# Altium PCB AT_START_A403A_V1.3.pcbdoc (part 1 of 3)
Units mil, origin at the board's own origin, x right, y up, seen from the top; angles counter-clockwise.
Board outline 6370 x 3956 mil, 2 copper layers (Top Layer, Bottom Layer); 182 components, 198 nets, 768 pads, 894 vias.
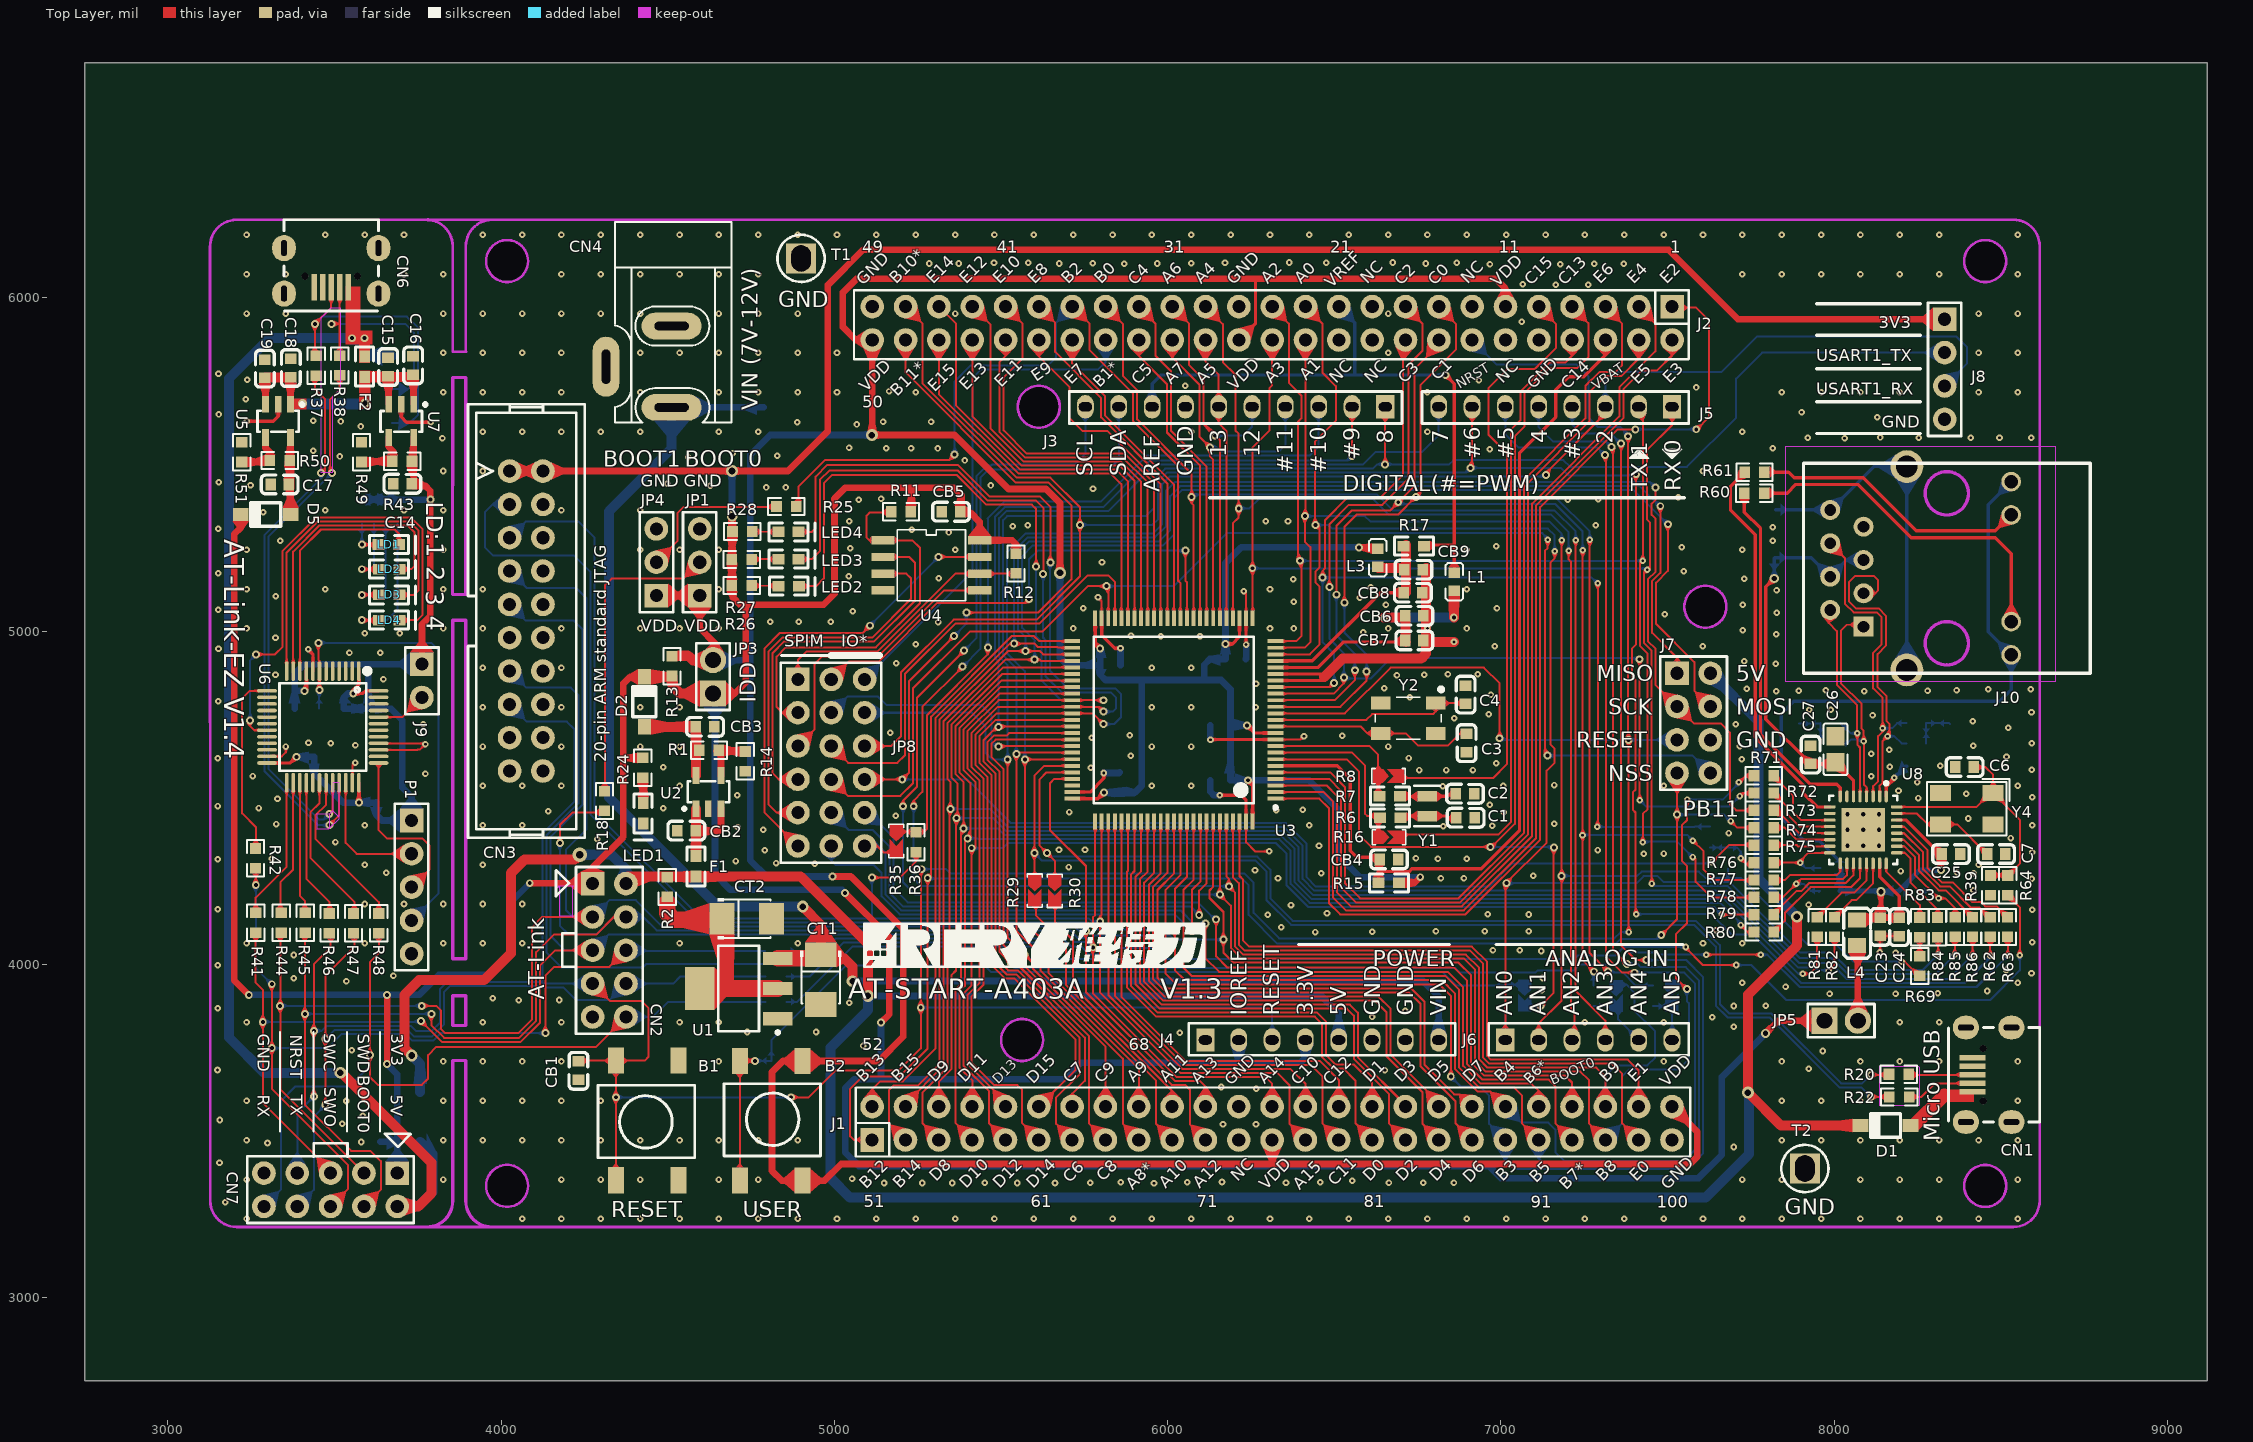
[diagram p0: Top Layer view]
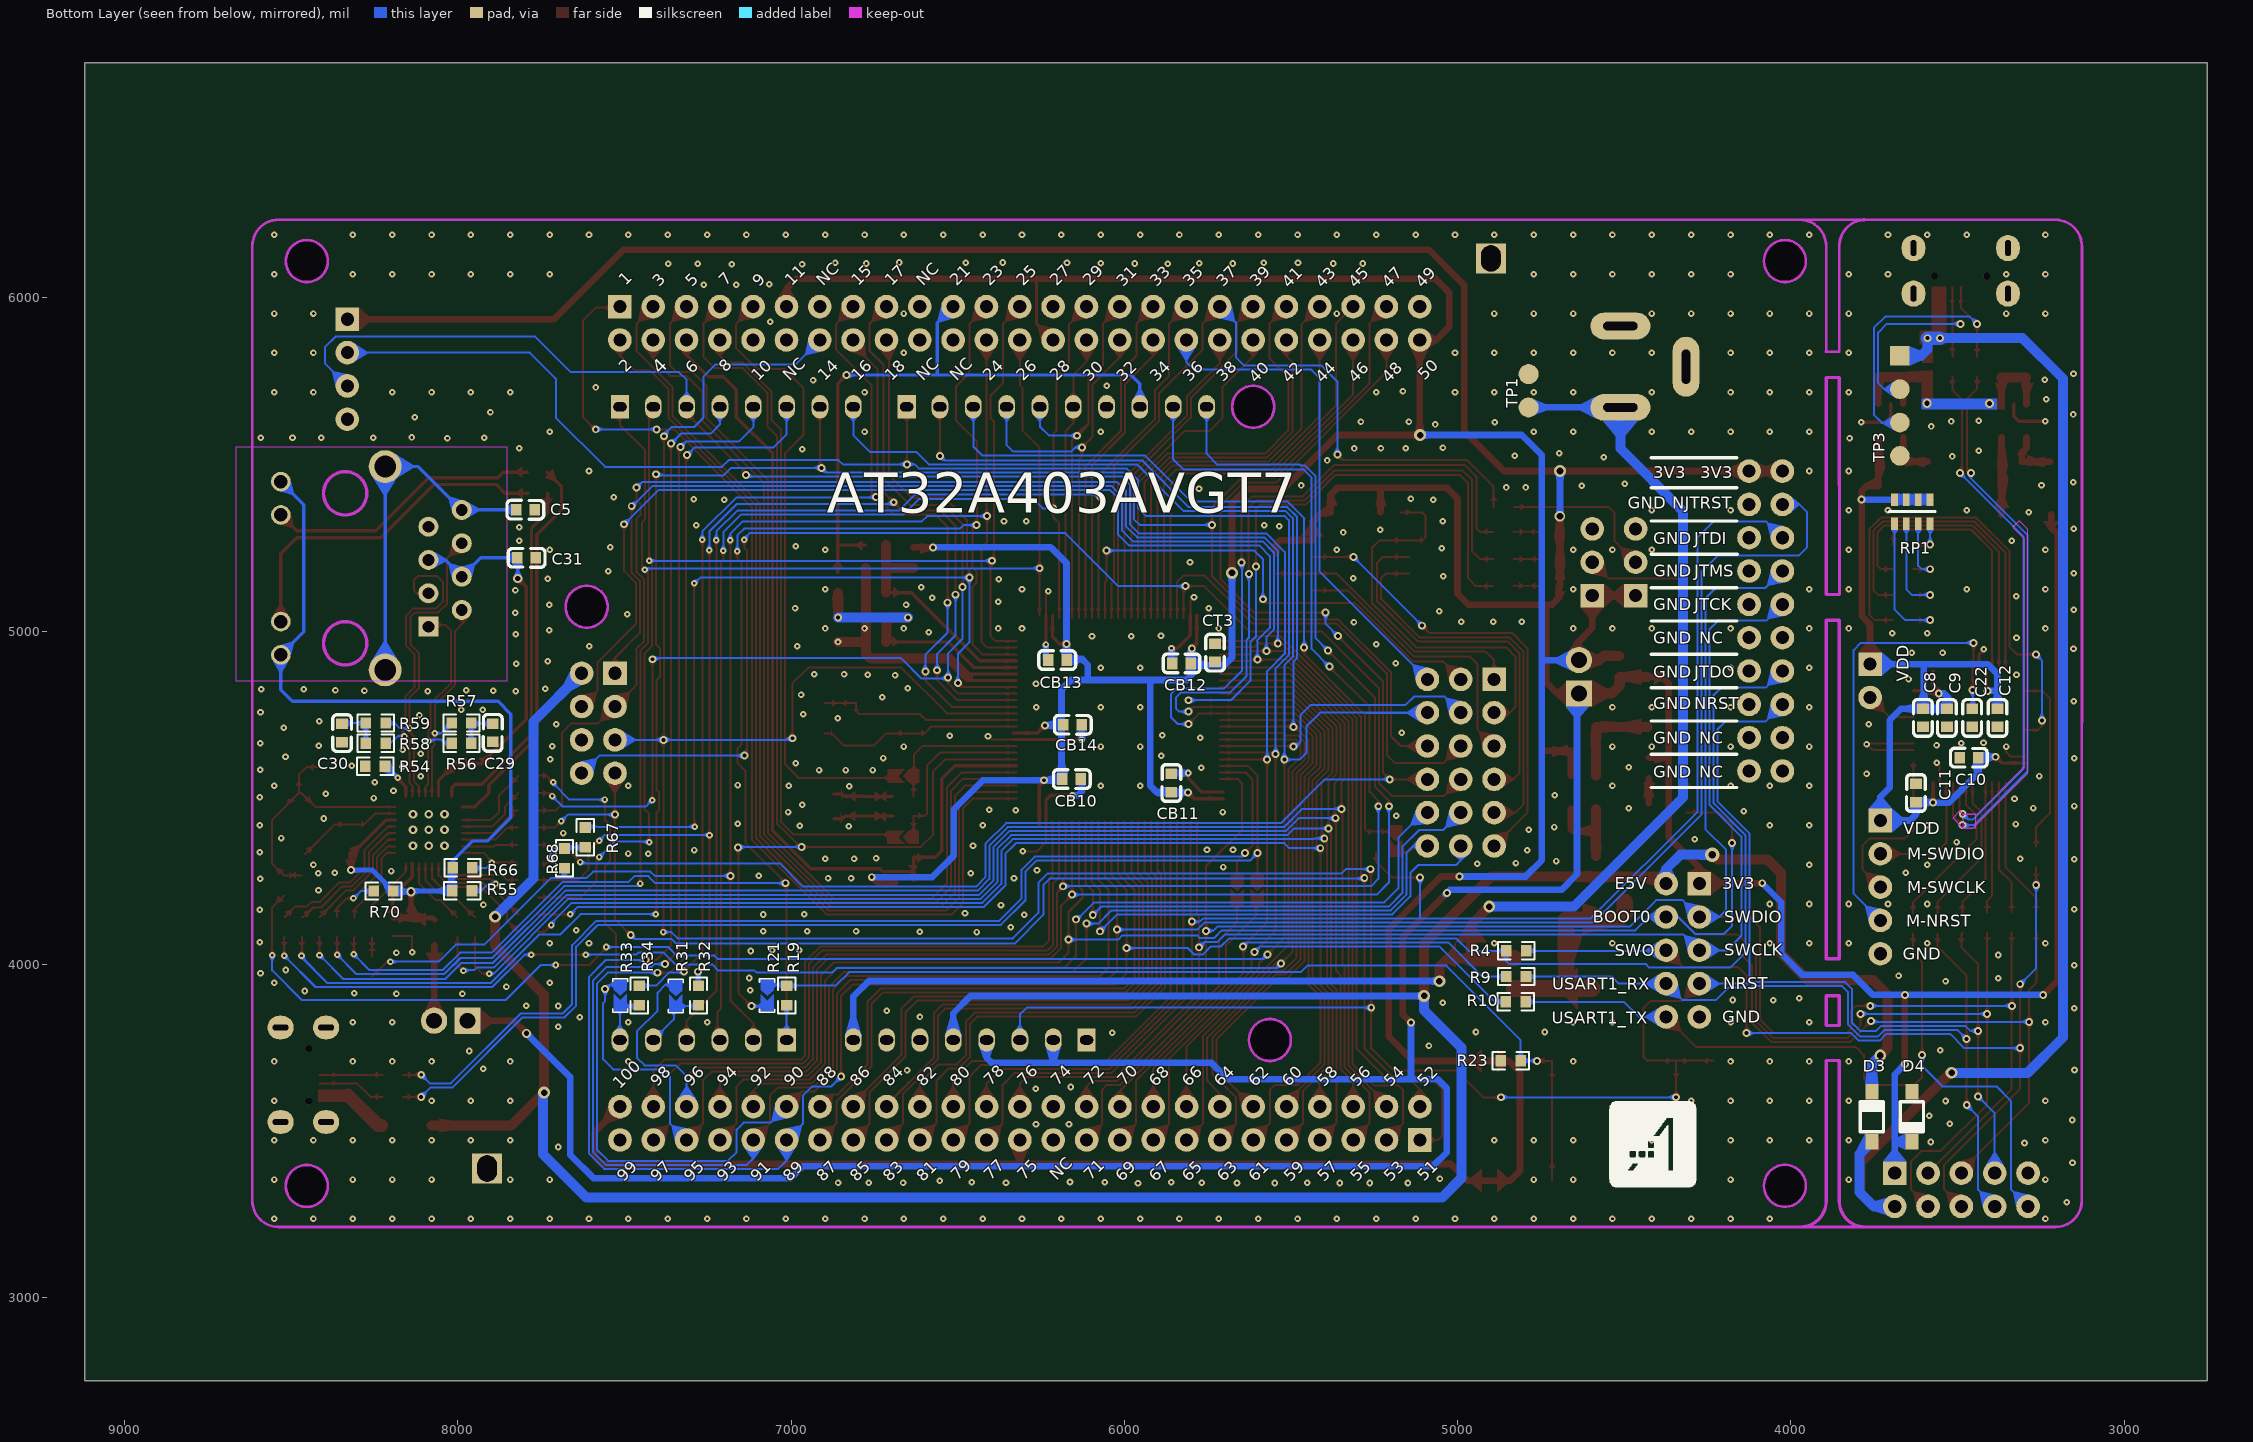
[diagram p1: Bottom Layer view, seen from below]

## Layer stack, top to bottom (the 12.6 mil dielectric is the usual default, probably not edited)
Top Layer: signal copper (thickness not stored)
Dielectric: dielectric 12.6, FR-4, Dk 4.8
Bottom Layer: signal copper (thickness not stored)

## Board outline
9120,2750 2750,2750 2750,6706 9120,6706
cut-out: 5676.27,5675.04 5676.27,5671.03 cw(c5613.28,5671.03) 5613.28,5608.03 cw(c5613.28,5673.03) 5548.28,5673.03 5548.28,5678.03 cw(c5608.28,5678.03) 5608.28,5738.03 5613.28,5738.03 cw(c5613.28,5675.04)
cut-out: 4080.65,6112.34 4080.65,6108.33 cw(c4017.66,6108.33) 4017.66,6045.33 cw(c4017.66,6110.33) 3952.66,6110.33 3952.66,6115.33 cw(c4012.66,6115.33) 4012.66,6175.33 4017.66,6175.33 cw(c4017.66,6112.34)
cut-out: 8517.27,6111.66 8517.27,6107.65 cw(c8454.28,6107.65) 8454.28,6044.65 cw(c8454.28,6109.65) 8389.28,6109.65 8389.28,6114.65 cw(c8449.28,6114.65) 8449.28,6174.65 8454.28,6174.65 cw(c8454.28,6111.66)
cut-out: 8516.42,3337.04 8516.42,3333.03 cw(c8453.43,3333.03) 8453.43,3270.03 cw(c8453.43,3335.03) 8388.43,3335.03 8388.43,3340.03 cw(c8448.43,3340.03) 8448.43,3400.03 8453.43,3400.03 cw(c8453.43,3337.04)
cut-out: 4080.65,3337.34 4080.65,3333.33 cw(c4017.66,3333.33) 4017.66,3270.33 cw(c4017.66,3335.33) 3952.66,3335.33 3952.66,3340.33 cw(c4012.66,3340.33) 4012.66,3400.33 4017.66,3400.33 cw(c4017.66,3337.34)
cut-out: 7676.27,5075.04 7676.27,5071.03 cw(c7613.28,5071.03) 7613.28,5008.03 cw(c7613.28,5073.03) 7548.28,5073.03 7548.28,5078.03 cw(c7608.28,5078.03) 7608.28,5138.03 7613.28,5138.03 cw(c7613.28,5075.04)
cut-out: 5626.27,3775.04 5626.27,3771.03 cw(c5563.28,3771.03) 5563.28,3708.03 cw(c5563.28,3773.03) 5498.28,3773.03 5498.28,3778.03 cw(c5558.28,3778.03) 5558.28,3838.03 5563.28,3838.03 cw(c5563.28,3775.04)

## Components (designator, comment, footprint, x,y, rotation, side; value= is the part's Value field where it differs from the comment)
B1 "PB,BLACK,SMD_2P" KEY_SOP_6*6 4344.58,3352.18 r90 top
B2 "PB,Blue,SMD_2P" KEY_SOP_6*6 4904.58,3710.18 r270 top
C1 "CL10C150JB8NNNC" C0603 6894,4440 r180 top
C2 "CL10C150JB8NNNC" C0603 6892,4512 r180 top
C3 "0603CG300J500NT" C0603 6897,4664 r90 top
C4 "0603CG300J500NT" C0603 6894,4809 r270 top
C5 "CC0603KRX7R9BB104" C0603 7797,5364 r180 bottom
C6 "0603CG300J500NT" C0603 8391,4592 r180 top
C7 "0603CG300J500NT" C0603 8486,4331 r0 top
C8 "CL10A475KO8NNNC" C0603 3604,4740 r90 bottom
C9 "CC0603KRX7R9BB104" C0603 3532,4740 r90 bottom
C10 "CC0603KRX7R9BB104" C0603 3466,4620 r180 bottom
C11 "CC0603KRX7R9BB104" C0603 3625,4514 r270 bottom
C12 "CC0603KRX7R9BB104" C0603 3380,4740 r90 bottom
C14 "CL10A106MA8NRNC" C0603 3704,5442 r0 top
C15 "CL10A106MA8NRNC" C0603 3661,5792 r270 top
C16 "CC0603KRX7R9BB104" C0603 3736,5797 r270 top
C17 "CL10A106MA8NRNC" C0603 3336,5440 r0 top
C18 "CL10A106MA8NRNC" C0603 3369,5789 r270 top
C19 "CC0603KRX7R9BB104" C0603 3291,5787 r270 top
C22 "CC0603KRX7R9BB104" C0603 3456,4740 r90 bottom
C23 "CL10A475KO8NNNC" C0603 8138,4113 r90 top
C24 "CC0603KRX7R9BB104" C0603 8195,4112 r90 top
C25 "CC0603KRX7R9BB104" C0603 8350,4331 r180 top
C26 "CL21A476MQYNNNE" C0805 8004,4645.37 r270 top
C27 "CC0603KRX7R9BB104" C0603 7929,4629 r270 top
C29 "CC0603KRX7R9BB104" C0603 7895,4695 r90 bottom
C30 "CC0603KRX7R9BB104" C0603 8347,4694 r90 bottom
C31 "CC0603KRX7R9BB104" C0603 7793.44,5220 r0 bottom
CB1 "CC0603KRX7R9BB104" C0603 4232,3681 r90 top
CB2 "CL10A105KB8NNNC" C0603 4556,4401 r0 top
CB3 "CL10A105KB8NNNC" C0603 4612,4713 r180 top
CB4 "CL10A105KB8NNNC" C0603 6664,4315 r180 top
CB5 "CC0603KRX7R9BB104" C0603 5350,5358 r0 top
CB6 "CL10A105KB8NNNC" C0603 6740,5046 r180 top
CB7 "CC0603KRX7R9BB104" C0603 6740,4972 r180 top
CB8 "CL10A105KB8NNNC" C0603 6736,5115 r0 top
CB9 "CC0603KRX7R9BB104" C0603 6738,5184 r0 top
CB10 "CC0603KRX7R9BB104" C0603 6158,4556 r0 bottom
CB11 "CC0603KRX7R9BB104" C0603 5859,4544 r270 bottom
CB12 "CC0603KRX7R9BB104" C0603 5828,4903 r180 bottom
CB13 "CC0603KRX7R9BB104" C0603 6201,4913 r180 bottom
CB14 "CC0603KRX7R9BB104" C0603 6155,4719 r0 bottom
CN1 "USB micro-B" USB_MIC_DIP 8414.55,3668.76 r0 top
CN2 "CON10A" HDR2X5 4274.58,4242.18 r270 top
CN3 "10X2P" JTAG_20 4075.58,5030.18 r270 top
CN4 "DC_JACK" DC10B 4341.58,6090.28 r270 top
CN6 "USB_micro B" USB_MIC_DIP 3490.36,6032.02 r90 top
CN7 "CON1" HDR2X5 3688.43,3373.78 r180 top
CT1 "CA45-B025K106T" CAP-SMD_L3.5-W2.8-R-RD 4959,3954 r90 top
CT2 "CA45-B025K106T" CAP-SMD_L3.5-W2.8-R-RD 4737,4137 r180 top
CT3 "CL10A475KO8NNNC" C0603 5728,4935 r270 bottom
D1 "DFLS130L" SOD-123 8153.95,3516.5 r0 top
D2 "DFLS130L" SOD-123 4429.95,4787.59 r270 top
D3 "DFLS130L" SOD-123 3756.95,3542.5 r270 bottom
D4 "SMF3.3A" SOD-123 3636.95,3542.5 r90 bottom
D5 "DFLS130L" SOD-123 3294.01,5349.78 r0 top
F1 "SMD0603B025TF" R0603#1 4585.16,4263.54 r90 top
F2 "SMD0603B025TF" R0603#1 3590.43,5823.67 r270 top
J1 "CONN EDGE 25X2" HEAD2*25 5113.28,3473.03 r0 top
J2 "CONN EDGE 25X2" HEAD2*25 7513.71,5973.46 r180 top
J3 "CON10" "HDR1X10 - 2#" 6653.28,5673.03 r180 top
J4 "CON8" "HDR1X8 - 2#" 6113.28,3773.03 r0 top
J5 "CON8" "HDR1X8 - 2#" 7513.28,5673.03 r180 top
J6 "CON6" "HDR1X6 -2#" 7013.28,3773.03 r0 top
J7 "CON8A" HDR2X4 7528.28,4873.61 r270 top
J8 "Header 4" HDR1X4 8331.46,5935.5 r270 top
J9 "1X2P_2.54M" HDR1X2 3762.43,4900.78 r270 top
J10 "RJ45 (TRJ201)" HR911105A 8338.04,5188.5 r270 top
JP1 "1X3P_2.54M" HDR1X3 4595.95,5106.5 r90 top
JP3 "1X2P_2.54M" HDR-TH_2P-P2.54-V-M 4636,4863 r90 top
JP4 "1X3P_2.54M" HDR1X3 4465.95,5106.5 r90 top
JP5 "1X2P_2.54M" HDR-TH_2P-P2.54-V-M 8021,3831 r0 top
JP8 "CON3*6" HDR3X6 4890.58,4855.18 r270 top
L1 "GZ1608D601TF" L0603 6860,5148 r270 top
L3 "GZ1608D601TF" L0603 6630,5220 r270 top
L4 "GZ2012D601TF" L0805 8069,4095 r90 top
LD1 "RED" LED0603 3632.47,5259.58 r0 top
LD2 "GREEN" LED0603 3633.43,5185.48 r0 top
LD3 "BLUE" LED0603 3633.47,5108.58 r0 top
LD4 "YELLOW" LED0603 3633.43,5032.58 r0 top
LED1 "RED" LED0603 4426.13,4483.46 r270 top
LED2 "RED" LED0603 4832.62,5134.61 r0 top
LED3 "YELLOW" LED0603 4831.95,5215.39 r0 top
LED4 "GREEN" LED0603 4831.62,5297.61 r0 top
P1 "Header 5" HDR1X5 3731.43,4431.78 r270 top
R1 "0603WAF5102T5E" R0603#2 4624,4642 r0 top
R2 "0603WAF0000T5E" R0603#2 4498.9,4232.03 r90 top
R4 "0603WAF4700T5E" R0603#2 4823.95,4040.5 r180 bottom
R6 "0603WAF0000T5E" R0603#1 6698,4440 r180 top
R7 "0603WAF0000T5E" R0603#1 6697,4505 r180 top
R8 "NC_SB-PAD" SB-PAD 6663,4565 r0 top
R9 "0603WAF4700T5E" R0603#2 4824.42,3963.51 r180 bottom
R10 "0603WAF4700T5E" R0603#2 4825.42,3887.51 r180 bottom
R11 "0603WAF1002T5E" R0603#2 5200,5358 r180 top
R12 "0603WAF1002T5E" R0603#2 5545,5203 r270 top
R13 "0603WAF0000T5E" R0603#2 4513,4895 r90 top
R14 "0603WAF1502T5E" R0603#2 4733,4609 r270 top
R15 "0603WAF0000T5E" R0603#1 6694,4245 r180 top
R16 "NC_SB-PAD" SB-PAD 6664,4381 r0 top
R17 "0603WAF0000T5E" R0603#1 6769,5255 r180 top
R18 "0603WAF1002T5E" R0603#2 4310,4490 r90 top
R19 "0603WAF0000T5E" R0603#2 7013.33,3906.35 r90 bottom
R20 "0603WAF220JT5E" R0603#2 8194,3670 r0 top
R21 "NC_SB-PAD" SB-PAD 7072,3906.28 r270 bottom
R22 "0603WAF220JT5E" R0603#2 8195,3602 r0 top
R23 "0603WAF1003T5E" R0603#2 4840.66,3711 r0 bottom
R24 "0603WAF1001T5E" R0603#2 4425,4590 r90 top
R25 "0603WAF1002T5E" R0603#2 4856,5374 r0 top
R26 "0603WAF1001T5E" R0603#2 4722,5137 r180 top
R27 "0603WAF1001T5E" R0603#2 4722,5215 r180 top
R28 "0603WAF1001T5E" R0603#2 4724,5299 r180 top
R29 "NC_SB-PAD" SB-PAD 5601,4221 r270 top
R30 "NC_SB-PAD" SB-PAD 5661,4220.72 r270 top
R31 "NC_SB-PAD" SB-PAD 7346,3905 r270 bottom
R32 "0603WAF0000T5E" R0603#2 7277.78,3906.66 r90 bottom
R33 "NC_SB-PAD" SB-PAD 7513,3907 r270 bottom
R34 "0603WAF0000T5E" R0603#2 7455.95,3906.65 r90 bottom
R35 "NC_SB-PAD" SB-PAD 5186,4370 r270 top
R36 "0603WAF0000T5E" R0603#2 5244.95,4366.5 r90 top
R37 "0603WAF220JT5E" R0603#2 3445,5796 r90 top
R38 "0603WAF220JT5E" R0603#2 3516,5797 r90 top
R39 "0603WAF1003T5E" R0603#2 8469,4237 r270 top
R41 "0603WAF330JT5E" R0603#2 3264,4125 r270 top
R42 "0603WAF330JT5E" R0603#2 3263,4318 r270 top
R43 "0603WAF4702T5E" R0603#2 3703,5510 r180 top
R44 "0603WAF330JT5E" R0603#2 3340,4125 r270 top
R45 "0603WAF330JT5E" R0603#2 3412,4125 r270 top
R46 "0603WAF330JT5E" R0603#2 3484,4123 r270 top
R47 "0603WAF330JT5E" R0603#2 3557,4123 r270 top
R48 "0603WAF330JT5E" R0603#2 3633,4123 r270 top
R49 "0603WAF1502T5E" R0603#2 3581,5537 r90 top
R50 "0603WAF5102T5E" R0603#2 3336,5512 r180 top
R51 "0603WAF1502T5E" R0603#2 3222,5537 r90 top
R54 "0603WAF6801T5E" R0603#2 8248,4594 r180 bottom
R55 "0603WAF1501T5E" R0603#2 7987,4221 r180 bottom
R56 "0603WAF499JT5E" R0603#2 7989,4663 r0 bottom
R57 "0603WAF499JT5E" R0603#2 7989,4724 r0 bottom
R58 "0603WAF499JT5E" R0603#2 8246,4663 r180 bottom
R59 "0603WAF499JT5E" R0603#2 8246,4724 r180 bottom
R60 "0603WAF3300T5E" R0603#2 7760,5414 r0 top
R61 "0603WAF3300T5E" R0603#2 7761,5477 r0 top
R62 "0603WAF0000T5E" R0603#2 8468,4112 r90 top
R63 "0603WAF499JT5E" R0603#2 8520,4112 r270 top
R64 "0603WAF499JT5E" R0603#2 8521,4237 r270 top
R66 "0603WAF4701T5E" R0603#2 7986,4290 r180 bottom
R67 "0603WAF0000T5E" R0603#2 7618,4381 r90 bottom
R68 "0603WAF0000T5E" R0603#2 7680,4318 r90 bottom
R69 "0603WAF0000T5E" R0603#2 8257,3995 r270 top
R70 "0603WAF4701T5E" R0603#2 8223,4220 r0 bottom
R71 "0603WAF0000T5E" R0603#2 7789,4566 r180 top
R72 "0603WAF0000T5E" R0603#2 7789,4514 r180 top
R73 "0603WAF0000T5E" R0603#2 7789,4462 r180 top
R74 "0603WAF0000T5E" R0603#2 7789,4410 r180 top
R75 "0603WAF0000T5E" R0603#2 7788.98,4357.53 r180 top
R76 "0603WAF0000T5E" R0603#2 7789,4305 r180 top
R77 "0603WAF0000T5E" R0603#2 7789,4253 r180 top
R78 "0603WAF0000T5E" R0603#2 7789,4201 r180 top
R79 "0603WAF0000T5E" R0603#2 7789,4149 r180 top
R80 "0603WAF0000T5E" R0603#2 7789,4097 r180 top
R81 "0603WAF0000T5E" R0603#2 7949,4112 r90 top
R82 "0603WAF0000T5E" R0603#2 8001,4112 r90 top
R83 "0603WAF0000T5E" R0603#2 8257,4111 r90 top
R84 "0603WAF0000T5E" R0603#2 8310,4111 r90 top
R85 "0603WAF0000T5E" R0603#2 8363,4112 r90 top
R86 "0603WAF0000T5E" R0603#2 8415,4112 r90 top
RP1 "1K" RP_4-0603 3688.82,5321.66 r90 bottom
T1 "Socket" TestPoint 4899.95,6118.29 r270 top
T2 "Socket" TestPoint 7911.95,3387.5 r270 top
TP1 "1X2P_2.54M" TEST_PAD_1x2p_2.54 4787,5721 r90 bottom
TP3 "1X4P_2.54F" "HDR1X4 - TOP" 3673.01,5825.78 r270 bottom
U1 "AMS1117-5.0" SOT223 4712.95,3927.5 r180 top
U2 "RT9080N-08GJ5" SOT-23-5 4684.95,4531.5 r90 top
U3 "AT32F407VGT7" LQFP100_14*14 6018.62,4733.5 r180 top
U4 "EN25QH128A" SOIC8_208 5290.95,5197.5 r270 top
U5 "RT9080N-08GJ5" SOT-23-5 3268.23,5615.67 r270 top
U6 "AT32F403ACCT7" LQFP-48_L7.0-W7.0-P0.50-LS9.0-BL 3464.9,4712.46 r180 top
U7 "RT9080N-08GJ5" SOT-23-5 3637.43,5615.6 r270 top
U8 "DM9162NP" DM9162NP 8087.21,4403.5 r270 top
Y1 "32.768KHz" "XTAL_SOP - FC-12M" 6778.58,4504.18 r270 top
Y2 "8MHz" SMD_5032_4P 6721.95,4738.5 r180 top
Y4 "X503225MSB4SI" CRYSTAL-SMD_4P-L5.0-W3.2-BL 8398,4467 r180 top

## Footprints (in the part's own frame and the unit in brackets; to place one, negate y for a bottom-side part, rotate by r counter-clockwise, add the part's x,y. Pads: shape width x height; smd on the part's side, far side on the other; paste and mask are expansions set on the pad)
C0603 [mm]
  rect 0.8x0.9 smd paste+0 mask+0.051: 1(-0.7,0) 2(0.7,0)
  silkscreen extent -1.41,-0.71 1.39,0.72
C0805 [mm]
  rect 1.41x1.35 smd paste-100 mask+0.051: 1(-1,0) 2(1,0)
  silkscreen extent -1.96,-0.9 1.96,0.9
CAP-SMD_L3.5-W2.8-R-RD [mil]
  rect 74.8x93.5 smd paste+0 mask+2: 1(74.8,0) 2(-74.7,0)
  silkscreen extent -72,-61 87,61
CRYSTAL-SMD_4P-L5.0-W3.2-BL [mm]
  rect 1.6x1.2 smd paste+0 mask+0.051: 1(-2,-1.2) 2(2,-1.2) 3(2,1.2) 4(-2,1.2)
  silkscreen extent -3.26,-2.26 3.03,2.03
DC10B [mil]
  oval 80x180 hole 25.59 slot 102.36 at 90 deg mask+2: 1(419.09,170) 2(175,170)
  oval 180x80 hole 25.59 slot 102.36 at 0 deg mask+2: 3(297.05,-26.85)
  silkscreen extent -138,0 465,350
DM9162NP [mm]
  oval 0.9x0.25 smd mask+0.051: 1(-2.55,1.75) 2(-2.55,1.25) 3(-2.55,0.75) 4(-2.55,0.25) 5(-2.55,-0.25) 6(-2.55,-0.75) 7(-2.55,-1.25) 8(-2.55,-1.75) 17(2.55,-1.75) 18(2.55,-1.25) 19(2.55,-0.75) 20(2.55,-0.25) 21(2.55,0.25) 22(2.55,0.75) 23(2.55,1.25) 24(2.55,1.75)
  oval 0.25x0.9 smd mask+0.051: 9(-1.75,-2.55) 10(-1.25,-2.55) 11(-0.75,-2.55) 12(-0.25,-2.55) 13(0.25,-2.55) 14(0.75,-2.55) 15(1.25,-2.55) 16(1.75,-2.55) 25(1.75,2.55) 26(1.25,2.55) 27(0.75,2.55) 28(0.25,2.55) 29(-0.25,2.55) 30(-0.75,2.55) 31(-1.25,2.55) 32(-1.75,2.55)
  rect 3.3x3.3 smd mask+0.051: 33(0,0)
  silkscreen extent -3.67,-2.6 2.6,2.6
HDR1X2 [mm]
  rect 1.8x1.8 hole 1 mask+0.051: 1(0,0)
  round 1.8 hole 1 mask+0.051: 2(2.54,0)
  silkscreen extent -1.27,-1.27 3.81,1.27
HDR1X3 [mm]
  rect 1.8x1.8 hole 1 mask+0.051: 1(0,0)
  round 1.8 hole 1 mask+0.051: 2(2.54,0) 3(5.08,0)
  silkscreen extent -1.27,-1.27 6.35,1.27
HDR1X4 [mm]
  rect 1.8x1.8 hole 1 mask+0.051: 1(0,0)
  round 1.8 hole 1 mask+0.051: 2(2.54,0) 3(5.08,0) 4(7.62,0)
  silkscreen extent -1.27,-1.27 8.89,1.27
"HDR1X4 - TOP" [mm]
  rect 1.5x1.5 smd mask+0.051: 1(0,0)
  round 1.5 smd mask+0.051: 2(2.54,0) 3(5.08,0) 4(7.62,0)
HDR1X5 [mm]
  rect 1.8x1.8 hole 1 mask+0.051: 1(0,0)
  round 1.8 hole 1 mask+0.051: 2(2.54,0) 3(5.08,0) 4(7.62,0) 5(10.16,0)
  silkscreen extent -1.27,-1.27 11.43,1.27
"HDR1X6 -2#" [mil]
  rect 55x70 hole 27.56 slot 39.37 at 0 deg mask+2: 1(0,0)
  oval 50x70 hole 27.56 slot 39.37 at 0 deg mask+2: 2(100,0) 3(200,0) 4(300,0) 5(400,0) 6(500,0)
  silkscreen extent -50,-46 550,50
"HDR1X8 - 2#" [mil]
  rect 55x70 hole 27.56 slot 39.37 at 0 deg mask+2: 1(0,0)
  oval 50x70 hole 27.56 slot 39.37 at 0 deg mask+2: 2(100,0) 3(200,0) 4(300,0) 5(400,0) 6(500,0) 7(600,0) 8(700,0)
  silkscreen extent -50,-46 750,50
"HDR1X10 - 2#" [mil]
  rect 55x70 hole 27.56 slot 39.37 at 0 deg mask+2: 1(0,0)
  oval 50x70 hole 27.56 slot 39.37 at 0 deg mask+2: 2(100,0) 3(200,0) 4(300,0) 5(400,0) 6(500,0) 7(600,0) 8(700,0) 9(800,0) 10(900,0)
  silkscreen extent -50,-46 949,50
HDR2X4 [mm]
  rect 1.8x1.8 hole 1 mask+0.051: 1(0,0)
  round 1.8 hole 1 mask+0.051: 2(0,2.54) 3(2.54,0) 4(2.54,2.54) 5(5.08,0) 6(5.08,2.54) 7(7.62,0) 8(7.62,2.54)
  silkscreen extent -1.27,-1.27 8.89,3.81
HDR2X5 [mm]
  rect 1.8x1.8 hole 1 mask+0.051: 1(0,0)
  round 1.8 hole 1 mask+0.051: 2(0,2.54) 3(2.54,0) 4(2.54,2.54) 5(5.08,0) 6(5.08,2.54) 7(7.62,0) 8(7.62,2.54) 9(10.16,0) 10(10.16,2.54)
  silkscreen extent -1.27,-1.27 11.43,3.81
HDR3X6 [mm]
  rect 1.8x1.8 hole 1 mask+0.051: 1(0,0)
  round 1.8 hole 1 mask+0.051: 2(0,2.54) 3(0,5.08) 4(2.54,0) 5(2.54,2.54) 6(2.54,5.08) 7(5.08,0) 8(5.08,2.54) 9(5.08,5.08) 10(7.62,0) 11(7.62,2.54) 12(7.62,5.08) 13(10.16,0) 14(10.16,2.54) 15(10.16,5.08) 16(12.7,0) 17(12.7,2.54) 18(12.7,5.08)
  silkscreen extent -1.27,-1.3 13.97,6.35
HDR-TH_2P-P2.54-V-M [mm]
  rect 2x2 hole 1.2 paste+0 mask+0.051: 1(-1.27,0)
  round 2 hole 1.2 paste+0 mask+0.051: 2(1.27,0)
  silkscreen extent -2.54,-1.27 2.54,1.27
HEAD2*25 [mm]
  rect 1.8x1.8 hole 1 mask+0.051: 1(0,0)
  round 1.8 hole 1 mask+0.051: 2(0,2.54) 3(2.54,0) 4(2.54,2.54) 5(5.08,0) 6(5.08,2.54) 7(7.62,0) 8(7.62,2.54) 9(10.16,0) 10(10.16,2.54) 11(12.7,0) 12(12.7,2.54) 13(15.24,0) 14(15.24,2.54) 15(17.78,0) 16(17.78,2.54) 17(20.32,0) 18(20.32,2.54) 19(22.86,0) 20(22.86,2.54) 21(25.4,0) 22(25.4,2.54) 23(27.94,0) 24(27.94,2.54) 25(30.48,0) 26(30.48,2.54) 27(33.02,0) 28(33.02,2.54) 29(35.56,0) 30(35.56,2.54) 31(38.1,0) 32(38.1,2.54) 33(40.64,0) 34(40.64,2.54) 35(43.18,0) 36(43.18,2.54) 37(45.72,0) 38(45.72,2.54) 39(48.26,0) 40(48.26,2.54) 41(50.8,0) 42(50.8,2.54) 43(53.34,0) 44(53.34,2.54) 45(55.88,0) 46(55.88,2.54) 47(58.42,0) 48(58.42,2.54) 49(60.96,0) 50(60.96,2.54)
  silkscreen extent -1.26,-1.26 62.36,4
HR911105A [mm]
  rect 1.524x1.524 hole 0.889 mask+0.051: 1(4.45,-6.35)
  round 1.524 hole 0.889 mask+0.051: 2(3.18,-8.89) 3(1.91,-6.35) 4(0.64,-8.89) 5(-0.63,-6.35) 6(-1.9,-8.89) 7(-3.17,-6.35) 8(-4.44,-8.89)
  round 1.5 hole 1.02 mask+0.051: 9(6.6,4.9) 10(4.064,4.9) 11(-4.064,4.9) 12(-6.6,4.9)
  round 2.5 hole 1.65 mask+0.051: 13(7.75,-3.048) 14(-7.75,-3.048)
  Board Outline Layer circle w0.051: c5.716,0 r1.65
  Board Outline Layer circle w0.051: c5.716,0 r1.65
  Board Outline Layer circle w0.051: c-5.714,0 r1.65
  Board Outline Layer circle w0.051: c-5.714,0 r1.65
  silkscreen extent -8,-10.92 8,10.92
JTAG_20 [mm]
  round 1.8 hole 1 mask+0.051: 1(-11.43,-1.27) 2(-11.43,1.27) 3(-8.89,-1.27) 4(-8.89,1.27) 5(-6.35,-1.27) 6(-6.35,1.27) 7(-3.81,-1.27) 8(-3.81,1.27) 9(-1.27,-1.27) 10(-1.27,1.27) 11(1.27,-1.27) 12(1.27,1.27) 13(3.81,-1.27) 14(3.81,1.27) 15(6.35,-1.27) 16(6.35,1.27) 17(8.89,-1.27) 18(8.89,1.27) 19(11.43,-1.27) 20(11.43,1.27)
  silkscreen extent -16.51,-4.45 16.51,4.45
KEY_SOP_6*6 [mm]
  rect 2x1.2 smd mask+0.051: 1(0,0) 1(9.119,0) 2(0,-4.775) 2(9.119,-4.775)
  silkscreen extent 1.73,-5.99 7.24,1.4
L0603 [mm]
  rect 0.8x0.864 smd paste-100 mask+0.051: 1(-0.7,0) 2(0.7,0)
  silkscreen extent -1.42,-0.65 1.41,0.67
L0805 [mil]
  rect 44.59x54.21 smd paste-3937.01 mask+2: 1(-38.04,0) 2(38.04,0)
  silkscreen extent -77,-40 73,40
LED0603 [mil]
  rect 36x32 smd mask+2: 1(-0.04,0.2) 2(60.96,0.2)
  silkscreen extent -28,-28 110,27
LQFP100_14*14 [mm]
  rect 1.2x0.3 smd mask+0.051: 1(-7.75,6) 2(-7.75,5.5) 3(-7.75,5) 4(-7.75,4.5) 5(-7.75,4) 6(-7.75,3.5) 7(-7.75,3) 8(-7.75,2.5) 9(-7.75,2) 10(-7.75,1.5) 11(-7.75,1) 12(-7.75,0.5) 13(-7.75,0) 14(-7.75,-0.5) 15(-7.75,-1) 16(-7.75,-1.5) 17(-7.75,-2) 18(-7.75,-2.5) 19(-7.75,-3) 20(-7.75,-3.5) 21(-7.75,-4) 22(-7.75,-4.5) 23(-7.75,-5) 24(-7.75,-5.5) 25(-7.75,-6) 51(7.75,-6) 52(7.75,-5.5) 53(7.75,-5) 54(7.75,-4.5) 55(7.75,-4) 56(7.75,-3.5) 57(7.75,-3) 58(7.75,-2.5) 59(7.75,-2) 60(7.75,-1.5) 61(7.75,-1) 62(7.75,-0.5) 63(7.75,0) 64(7.75,0.5) 65(7.75,1) 66(7.75,1.5) 67(7.75,2) 68(7.75,2.5) 69(7.75,3) 70(7.75,3.5) 71(7.75,4) 72(7.75,4.5) 73(7.75,5) 74(7.75,5.5) 75(7.75,6)
  rect 0.3x1.2 smd mask+0.051: 26(-6,-7.75) 27(-5.5,-7.75) 28(-5,-7.75) 29(-4.5,-7.75) 30(-4,-7.75) 31(-3.5,-7.75) 32(-3,-7.75) 33(-2.5,-7.75) 34(-2,-7.75) 35(-1.5,-7.75) 36(-1,-7.75) 37(-0.5,-7.75) 38(0,-7.75) 39(0.5,-7.75) 40(1,-7.75) 41(1.5,-7.75) 42(2,-7.75) 43(2.5,-7.75) 44(3,-7.75) 45(3.5,-7.75) 46(4,-7.75) 47(4.5,-7.75) 48(5,-7.75) 49(5.5,-7.75) 50(6,-7.75) 76(6,7.75) 77(5.5,7.75) 78(5,7.75) 79(4.5,7.75) 80(4,7.75) 81(3.5,7.75) 82(3,7.75) 83(2.5,7.75) 84(2,7.75) 85(1.5,7.75) 86(1,7.75) 87(0.5,7.75) 88(0,7.75) 89(-0.5,7.75) 90(-1,7.75) 91(-1.5,7.75) 92(-2,7.75) 93(-2.5,7.75) 94(-3,7.75) 95(-3.5,7.75) 96(-4,7.75) 97(-4.5,7.75) 98(-5,7.75) 99(-5.5,7.75) 100(-6,7.75)
  silkscreen extent -7.88,-6.35 6.09,6.8
LQFP-48_L7.0-W7.0-P0.50-LS9.0-BL [mm]
  oval 0.27x1.5 smd paste+0 mask+0.05: 1(-2.75,-4.25) 2(-2.25,-4.25) 3(-1.75,-4.25) 4(-1.25,-4.25) 5(-0.75,-4.25) 6(-0.25,-4.25) 7(0.25,-4.25) 8(0.75,-4.25) 9(1.25,-4.25) 10(1.75,-4.25) 11(2.25,-4.25) 12(2.75,-4.25) 25(2.75,4.25) 26(2.25,4.25) 27(1.75,4.25) 28(1.25,4.25) 29(0.75,4.25) 30(0.25,4.25) 31(-0.25,4.25) 32(-0.75,4.25) 33(-1.25,4.25) 34(-1.75,4.25) 35(-2.25,4.25) 36(-2.75,4.25)
  oval 1.5x0.27 smd paste+0 mask+0.05: 13(4.25,-2.75) 14(4.25,-2.25) 15(4.25,-1.75) 16(4.25,-1.25) 17(4.25,-0.75) 18(4.25,-0.25) 19(4.25,0.25) 20(4.25,0.75) 21(4.25,1.25) 22(4.25,1.75) 23(4.25,2.25) 24(4.25,2.75) 37(-4.25,2.75) 38(-4.25,2.25) 39(-4.25,1.75) 40(-4.25,1.25) 41(-4.25,0.75) 42(-4.25,0.25) 43(-4.25,-0.25) 44(-4.25,-0.75) 45(-4.25,-1.25) 46(-4.25,-1.75) 47(-4.25,-2.25) 48(-4.25,-2.75)
  silkscreen extent -3.59,-4.46 3.3,3.34
R0603#1 [mil]
  rect 36x32 smd mask+2: 1(-0.04,0.2) 2(60.96,0.2)
  silkscreen extent -28,-27 89,27
R0603#2 [mil]
  rect 31.75x34.02 smd paste-3937.01 mask+2: 1(-29.66,0) 2(29.66,0)
  silkscreen extent -55,-26 55,26
RP_4-0603 [mm]
  rect 0.95x0.55 smd mask+0.051: 1(0,-2.7) 4(0,0) 5(1.85,0) 8(1.85,-2.7)
  rect 0.95x0.5 smd mask+0.051: 2(0,-1.8) 3(0,-0.9) 6(1.85,-0.9) 7(1.85,-1.8)
  silkscreen extent 0.94,-3.1 0.94,0.43
SB-PAD [mil]
  Top Layer region: -47.24,-19.69 -47.24,19.69 -16.45,19.68 1,0 -17.05,-19.69
  Top Layer region: -4.69,19.68 15,0 -4.69,-19.69 47.24,-19.69 47.24,19.69
  silkscreen extent -50,-23 50,23
SMD_5032_4P [mm]
  rect 1.5x1 smd mask+0.051: 1(-2.1,-1.15) 2(2.1,-1.15) 3(2.1,1.15) 4(-2.1,1.15)
  silkscreen extent -2.65,-2.35 2.5,1.6
SOD-123 [mm]
  rect 1.2x1 smd mask+0.051: 1(1.905,0) 2(-1.905,0)
  silkscreen extent -1.14,-0.89 1.14,0.89
SOIC8_208 [mil]
  rect 25x70 smd paste+4 mask+2: 1(-75,-145) 2(-25,-145) 3(25,-145) 4(75,-145) 5(75,145) 6(25,145) 7(-25,145) 8(-75,145)
  silkscreen extent -106,-102 106,102
SOT223 [mm]
  rect 2.25x1 smd mask+0.051: 1(-2.975,2.3) 2(-2.975,0) 3(-2.975,-2.3)
  rect 2.25x3.25 smd mask+0.051: 4(2.975,0)
  silkscreen extent -3.1,-3.25 1.55,3.47
SOT-23-5 [mil]
  rect 50x20 smd mask+2: 1(-65,100) 2(-65,63) 3(-65,25) 4(35,25) 5(35,100)
  silkscreen extent -65,1 18,135
TEST_PAD_1x2p_2.54 [mil]
  round 60 smd mask+2: 1(-50,0) 2(50,0)
TestPoint [mm]
  rect 2.3x2.3 hole 1.5 slot 2 at 0 deg mask+0.051: 1(0,0)
  silkscreen extent -1.8,-1.8 1.8,1.8
USB_MIC_DIP [mm]
  rect 2x0.4 smd mask+0.051: 1(0,-1.3) 2(0,-0.65) 3(0,0) 4(0,0.65) 5(0,1.3)
  oval 2x1.8 hole 0.45 slot 1.2 at 0 deg mask+0.051: 6(-0.495,-3.6) 7(2.975,-3.6) 8(2.975,3.6) 9(-0.495,3.6)
  round 0.5 hole 0.55 unplated mask+0.051: MH1(0.825,2) MH2(0.825,-2)
  silkscreen extent -1.82,-3.6 5.12,3.6
"XTAL_SOP - FC-12M" [mm]
  rect 0.8x1.5 smd mask+0.051: 1(0,0) 2(1.5,0)
  silkscreen extent -0.81,-0.99 2.29,0.94

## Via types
v1: diameter 19.68, hole 7.87, Top Layer to Bottom Layer, 702 vias
v2: diameter 23.62, hole 11.81, Top Layer to Bottom Layer, 166 vias
v3: diameter 35.43, hole 19.68, Top Layer to Bottom Layer, 10 vias
v4: diameter 25.98, hole 12.99, Top Layer to Bottom Layer, 9 vias
v5: diameter 27.56, hole 15.75, Top Layer to Bottom Layer, 5 vias
v6: diameter 43.31, hole 21.65, Top Layer to Bottom Layer, 1 vias
v7: diameter 31.5, hole 19.68, Top Layer to Bottom Layer, 1 vias

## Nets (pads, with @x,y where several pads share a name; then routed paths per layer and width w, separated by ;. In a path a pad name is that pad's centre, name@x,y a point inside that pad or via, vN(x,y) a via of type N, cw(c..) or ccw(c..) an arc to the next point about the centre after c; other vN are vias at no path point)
3V3: CB5.2 CN2.1 CN3.1 CN3.2 CN7.1 D2.2 D4.2 D5.2 J4.2 J4.4 J8.1 JP3.1 JP5.1 R11.1 R12.1 R13.1 R24.2 R26.2 R27.2 R28.2 U4.8 | length 18025.5
  Top Layer w19.68: 7789.61,5935.5 J8.1@8331.46,5935.5
  Top Layer w20: D5.2@3219.01,5349.78 3219.01,5310.44 3199.01,5290.44 3199.01,3952.44 v2(3242.95,3908.5) ; v2(3657.95,3700.5) v2(3657.95,3908.5) ; CN3.1@4025.58,5480.18 CN3.2@4125.58,5480.18 4860.58,5480.18 4980.58,5600.18 4980.58,6038.18 5086.39,6144 7502.76,6144 7711.26,5935.5 7789.61,5935.5 ; v2(4085.95,4243.5) 4273.26,4243.5 CN2.1@4274.58,4242.18 4274.58,4290.12 4366.95,4382.5 4366.95,4619.5 ; R24.2@4426.95,4619.5 4366.95,4619.5 ; D2.2@4429.95,4862.59 4387.06,4862.59 4366.95,4842.49 4366.95,4619.5 ; JP3.1@4641.58,4812.21 4700.95,4812.21 4733.56,4844.82 4733.56,5079.21 ; v7(4692.87,5345.18) 4692.87,5139.39 4695.87,5136.39 4695.87,5100.29 4716.95,5079.21 4733.56,5079.21 ; v2(5032.26,4214.5) 5164.46,4082.3 5164.46,3850.01 v2(5139.95,3825.5) ; R11.1@5231.54,5356.39 5231.54,5430.39 ; R12.1@5544.95,5233.5 5544.95,5260.5 5532.95,5272.5 U4.8@5435.95,5272.5 5435.95,5327.57 5408.12,5355.4 5381.32,5355.4 5381.32,5408.44 5359.37,5430.39 5231.54,5430.39 ; v5(7794,3793) 7832,3831 JP5.1@7971,3831 ; 4733.56,5079.21 4967.6,5079.21 5000.58,5112.18 5000.58,5397.5 5033.47,5430.39 5231.54,5430.39
  Top Layer w30: D2.2@4429.95,4862.59 R13.1@4514.45,4862.59 ; R13.1@4514.48,4862.56 4514.48,4834.97 4537.24,4812.21 JP3.1@4641.58,4812.21
  Bottom Layer w10: J8.1@8331.46,5935.5 J8.1@8337.76,5941.8
  Bottom Layer w20: v2(3242.95,3908.5) v2(3657.95,3908.5) 3753.5,3908.5 3813.5,3968.5 3965.02,3968.5 4028.95,4032.44 4028.95,4186.5 v2(4085.95,4243.5) ; D4.2@3636.95,3467.5 3688.4,3467.5 ; v2(3657.95,3700.5) 3688.43,3670.02 3688.43,3467.47 CN7.1@3688.43,3373.78 ; JP3.1@4641.58,4812.21 4641.58,4270.21 4688.29,4223.5 5023.26,4223.5 v2(5032.26,4214.5) v2@5036.58,4210.18 ; v7(4692.87,5345.18) v3(4692.87,5480.42) ; v2(5139.95,3825.5) 5139.95,3655.5 ; 6213.28,3705.18 6398.58,3705.18 6413.28,3719.89 J4.4@6413.28,3773.03 ; J4.2@6213.28,3773.03 6213.28,3706.48 6211.98,3705.18 5739.58,3705.18 5689.89,3655.5 5139.95,3655.5 ; v5(7794,3793) 7663,3662 7663,3428.55 7592.95,3358.5 6999.95,3358.5 6963.95,3394.5 5073.95,3394.5 5032.26,3436.19 5032.26,3627.81 5059.95,3655.5 5139.95,3655.5
3V3E: C23.2 C24.2 C25.2 J10.9 J10.12 L4.2 R55.1 R66.1 R70.1 U8.23 U8.30 | length 2982.7
  Top Layer w10: U8.23@8136.42,4303.1 8136.42,4262.58 8195,4204 C24.2@8195,4139.56 ; U8.30@8187.6,4433.03 8215.97,4433.03 8318,4331 C25.2@8322.44,4331
  Top Layer w15: L4.2@8069,4133.04 8075.52,4139.56 C24.2@8195,4139.56 ; C23.2@8138,4140.56 8140,4142.56 v5(8140,4218) ; v2(8320,4283) 8320,4328.56 C25.2@8322.44,4331
  Bottom Layer w10: R66.1@8015.66,4290 8015.66,4311.34 7957,4370 7911,4370 7841,4440 7841,4751 7879,4789 8496,4789 8530.95,4823.95 J10.9@8530.95,4928.66 8462,4997.61 8462,5379.39 J10.12@8530.95,5448.34
  Bottom Layer w15: R66.1@8019.95,4288.5 8019.95,4223.18 8017.27,4220.5 8137.5,4220.5 v5(8140,4218) 8191.34,4218 R70.1@8193.34,4220 8256.34,4283 v2(8320,4283)
5V: CN2.2 D1.2 D3.2 F1.1 J4.5 J7.2 R2.2 | length 9260.2
  Top Layer w30: v3(3731.95,3726.5) 3709.95,3748.5 3709.95,3908.5 3753.95,3952.5 3949.02,3952.5 4028.95,4032.44 4028.95,4273.5 4069.45,4314 4220.85,4314 v6(4235.95,4329.1) ; CN2.2@4374.58,4242.18 4395.89,4263.5 F1.1@4584.95,4263.5 4898.95,4263.5 5100.58,4061.88 v3(5100.58,3905.18) ; v3(7888,4143) 7888,4056 7741,3909 v3(7741,3615.13) 7839.63,3516.5 D1.2@8078.95,3516.5
  Bottom Layer w20: v3(5100.58,3905.18) 6461.58,3905.18 6513.28,3853.48 J4.5@6513.28,3773.03 ; J7.2@7628.28,4872.63 J7.2@7628.28,4873.61
  Bottom Layer w30: v3(3731.95,3726.5) 3756.95,3701.5 D3.2@3756.95,3617.5 ; v6(4235.95,4329.1) 4331.35,4329.1 4374.58,4285.88 CN2.2@4374.58,4242.18 ; v3(5100.58,3905.18) 5100.58,3862.5 4988.95,3750.88 4988.95,3358.05 5047,3300 7613.45,3300 7743.95,3430.5 7743.95,3613.05 v3@7742,3615 ; J7.2@7628.28,4873.61 7773.14,4728.75 7773.14,4257.86 v3(7888,4143)
$1N760: LD1.1 RP1.1 | length 111.5
  Top Layer w6: v2(3582.95,5259.78) LD1.1@3632.43,5259.78
  Bottom Layer w6: RP1.1@3582.52,5321.66 3582.52,5260.22 v2(3582.95,5259.78)
$1N761: LD2.1 RP1.2 | length 217.4
  Top Layer w6: v2(3581.95,5185.69) LD2.1@3633.39,5185.69
  Bottom Layer w6: v2(3581.95,5185.69) 3607.62,5185.69 3617.95,5196.02 RP1.2@3617.95,5321.66
$1N762: LD3.1 RP1.3 | length 326.6
  Top Layer w6: v2(3581.95,5108.5) 3633.15,5108.5 LD3.1@3633.43,5108.78
  Bottom Layer w6: v2(3581.95,5108.5) 3636.95,5108.5 3653.39,5124.93 RP1.3@3653.39,5321.66
$1N763: LD4.1 RP1.4 | length 428.7
  Top Layer w6: v2(3581.95,5032.78) LD4.1@3633.39,5032.78
  Bottom Layer w6: v2(3581.95,5032.78) 3657.24,5032.78 3688.82,5064.36 RP1.4@3688.82,5321.66
$1N774: C15.2 C16.2 C18.2 C19.2 F2.2 U5.1 U5.3 U7.1 U7.3 | length 541.8
  Top Layer w20: U5.3@3293.23,5680.67 3293.23,5759.63 C19.2@3294.23,5760.63 ; U5.1@3368.23,5680.67 C18.2@3368.23,5760.63 ; U7.3@3662.43,5682.67 C15.2@3662.43,5760.84 ; U7.1@3737.43,5682.67 C16.2@3737.43,5762.67
  Top Layer w30: C19.2@3294.23,5760.63 C18.2@3368.23,5760.63 ; F2.2@3590.64,5762.71 C16.2@3737.39,5762.71 ; C15.2@3662.43,5760.84 C15.2@3664.23,5762.63
  other v5: 3403.95,5682.5 3591.43,5683.78
$1N912: R50.2 R51.1 U5.4 | length 163.6
  Top Layer w20: R51.1@3222.01,5507.78 3307.01,5507.78 3307.01,5535.78 3293.23,5549.57 U5.4@3293.23,5580.67
$1N913: R43.2 R49.1 U7.4 | length 163.5
  Top Layer w20: R49.1@3590.01,5508.71 3676.01,5508.71 3676.01,5539.71 3662.43,5553.29 U7.4@3662.43,5580.6
$2N621: JP4.2 R25.1 | length 483.2
  Top Layer w6: JP4.2@4465.95,5206.5 4529.95,5270.5 4529.95,5354.5 4548.43,5372.98 R25.1@4830.95,5372.98
$2N622: C2.2 R7.1 Y1.1 | length 179.1
  Top Layer w10: R7.1@6695.54,4503.76 6778.15,4503.76 Y1.1@6778.58,4504.18 6840.61,4504.18 6847.61,4511.18 C2.2@6871.58,4511.18
$2N631: R7.2 U3.9 | length 444.3
  Top Layer w6: U3.9@6323.73,4654.76 6606,4654.76 6631.64,4629.12 6631.64,4559.21 6632.6,4558.25 R7.2@6632.6,4503.78
$2N641: C1.2 R6.1 Y1.2 | length 178.8
  Top Layer w10: R6.1@6695.08,4445.26 6778.44,4445.26 Y1.2@6778.58,4445.13 6838.58,4445.13 6846.52,4437.18 C1.2@6870.58,4437.18
$2N654: R6.2 U3.8 | length 528
  Top Layer w6: U3.8@6323.73,4635.07 6553.69,4635.07 6591.58,4597.18 6591.58,4452.18 6598.47,4445.29 R6.2@6632.15,4445.29 ; 6632.12,4389.18 R6.2@6632.12,4445.25
$2N678: JP1.2 R18.2 | length 933.1
  Top Layer w6: R18.2@4311.58,4517.18 4311.58,5137.18 4331.58,5157.18 4546.64,5157.18 JP1.2@4595.95,5206.5
$2N696: C4.2 U3.13 Y2.1 | length 610.3
  Top Layer w6: U3.13@6323.73,4733.5 6596.28,4733.5 6613.28,4750.5 6796.13,4750.5 6804.63,4759 Y2.1@6804.63,4783.77 C4.2@6898.71,4783.77
$2N697: C3.2 U3.12 Y2.3 | length 614.5
  Top Layer w6: U3.12@6323.73,4713.81 6578.64,4713.81 6599.23,4693.22 Y2.3@6639.28,4693.22 6714.32,4693.22 6751.36,4656.18 6840.26,4656.18 6877.34,4693.26 C3.2@6898.95,4693.26
$3N563: LED1.1 R24.1 | length 75.3
  Top Layer w20: LED1.1@4426.33,4483.5 4426.95,4484.12 R24.1@4426.95,4558.5
$3N570: CB3.2 D2.1 R1.1 U2.5 | length 301
  Top Layer w30: D2.1@4429.95,4712.59 4584.86,4712.59 4584.95,4712.5 U2.5@4584.95,4566.5
$3N571: CT2.1 R2.1 U1.2 U1.4 | length 657.5
  Top Layer w50: R2.1@4498.89,4187.03 4498.89,4153.56 4518.95,4133.5 4673.95,4133.5 4673.95,3928.5 4674.95,3927.5 ; U1.4@4595.83,3927.5 4674.95,3927.5 ; U1.2@4830.08,3927.5 4674.95,3927.5
$3N572: CB2.2 F1.2 U2.1 U2.3 | length 280
  Top Layer w20: CB2.2@4584.95,4399.18 4652.64,4399.18 4659.95,4406.5 U2.3@4659.95,4466.5
  Top Layer w30: F1.2@4584.95,4324.5 4584.95,4399.18 U2.1@4584.95,4466.5
$3N721: B2.2 R19.2 R23.1 | length 2895
  Top Layer w6: B2.2@4716.58,3351.18 B2.2@4716.58,3710.18 4716.92,3710.53 v2(4761.58,3710.53)
  Bottom Layer w6: v2(4761.58,3710.53) 4810.58,3710.53 4810.58,3772.75 5033.82,3996 5451,3996 5470.02,3976.98 6826.02,3976.98 6866.99,3936.01 R19.2@7013.33,3936.01 ; R19.2@7013.25,3939.12 7071.94,3939.12 ; R19.2@7013.25,3941.41 R19.2@7013.85,3940.82
$3N724: LED3.1 R27.1 | length 88.1
  Top Layer w6: R27.1@4743.87,5214.39 R27.1@4754.87,5214.39 ; R27.1@4754.87,5215.39 4755.08,5215.59 LED3.1@4831.91,5215.59
$3N725: LED4.1 R28.1 | length 89.3
  Top Layer w6: R28.1@4742.87,5297.39 4830.15,5298.39 4831.15,5297.39 LED4.1@4831.58,5297.81
$3N732: LED2.1 R26.1 | length 87.4
  Top Layer w6: R26.1@4745.87,5135.39 4831,5136.39 LED2.1@4832.58,5134.81
$3N736: R1.2 R14.1 U2.4 | length 165.8
  Top Layer w20: U2.4@4659.95,4566.5 4659.95,4626.5 4645.95,4640.5 R14.1@4731.95,4640.5
$4N291: J1.21 | length 919.2
  Top Layer w6: 5662.03,4182.12 5662.03,4125.97 5715.96,4072.04 5715.96,3934.8 6012.23,3638.53 6052.23,3638.53 6066.58,3624.18 6066.58,3520.59 J1.21@6113.71,3473.46
$4N318: J1.20 | length 778.3
  Top Layer w6: 5604.33,4182.2 5604.33,4147.83 5694.76,4057.41 5694.76,3939.03 6013.71,3620.08 J1.20@6013.71,3573.46
$4N381: J3.3 R36.2 | length 2303.3
  Top Layer w6: 5187.16,4398.43 5269.04,4397.96 5278.58,4407.5 5278.58,4748.17 5460.28,4929.87 v2@5460.28,4950.14
  Bottom Layer w6: v2(5460.63,4950.5) 5460.63,5336.81 5460.95,5337.12 5459.95,5338.12 5510.01,5388.18 5799.58,5388.18 5937.58,5526.18 6425.58,5526.18 6453.28,5553.89 J3.3@6453.28,5673.03
$4N511: J6.5 R32.1 | length 201.4
  Bottom Layer w6: R32.1@7277.79,3875.19 7277.95,3875.03 7351.5,3875.03 ; 7351.49,3875.02 7351.49,3834.83 J6.5@7413.28,3773.03
$4N519: J6.6 R34.1 | length 160
  Bottom Layer w6: R34.1@7455.97,3874.95 7513.34,3874.95 7513.58,3875.18 7513.58,3773.33 J6.6@7513.28,3773.03
$5N882: R54.2 U8.1 | length 118.4
  Top Layer w10: U8.1@8156.1,4503.89 8156.1,4533.1 8180,4557 v1(8180,4560)
  Bottom Layer w10: v1(8180,4560) 8214,4594 R54.2@8218.34,4594
$5N889: C30.2 R58.1 R59.1 | length 133.4
  Bottom Layer w6: R58.1@8275.66,4663 R59.1@8275.66,4724 8344.56,4724 C30.2@8347,4721.56
$5N896: J10.10 R60.2 | length 1041.7
  Top Layer w10: R60.2@7789.66,5414 7859,5414 7885,5440 8071,5440 8231,5280 8483,5280 8530.95,5232.05 J10.10@8530.95,5028.5
$5N898: J10.11 R61.2 | length 832.9
  Top Layer w10: R61.2@7790.66,5477 7863,5477 7880,5460 8086.63,5460 8245.63,5301 8483.45,5301 J10.11@8530.95,5348.5
$5N910: C29.2 R56.1 R57.1 | length 125.9
  Bottom Layer w6: C29.2@7895,4722.56 7957.9,4722.56 R57.1@7959.34,4724 R56.1@7959.34,4663
$5N1007: R67.1 R68.2 R76.2 | length 151.1
  Top Layer w6: v1(7720,4318) 7737.5,4300.5 R76.2@7745.5,4300.5
  Bottom Layer w6: R67.1@7626.88,4350.03 7708.53,4349.96 7720,4338.5 v1(7720,4318)
$5N1010: R69.1 R83.1 | length 56.7
  Top Layer w6: R69.1@8257,4024.66 R83.1@8257,4081.34
$5N34535: JP5.2 L4.1 | length 226.8
  Top Layer w20: L4.1@8069,4056.96 8071,4054.96 JP5.2@8071,3831
ATLINK_5V: CN6.1 CN7.2 D3.1 F2.1 TP3.1 | length 3821.1
  Top Layer w30: v3(3517.95,3674.5) 3521.5,3674.5 3790.95,3405.05 3790.95,3313.5 3751.24,3273.78 CN7.2@3688.43,3273.78
  Bottom Layer w30: v3(3517.95,3674.5) 3289.5,3674.5 3183.84,3780.16 3183.84,5757.84 3304.78,5878.78 v2(3552.95,5878.78) ; v2(3590.64,5878.78) 3590.64,5845.16 3610.01,5825.78 TP3.1@3673.01,5825.78 ; CN7.2@3688.43,3273.78 3751.24,3273.78 3793.95,3316.5 3793.95,3430.5 D3.1@3756.95,3467.5
  Bottom Layer w40: v2(3552.95,5878.78) v2(3590.64,5878.78)
ATLK_BOOT0: R45.1 U6.27 | length 395.7
  Top Layer w6: U6.27@3396,4545.14 3396.01,4205.91 3411.43,4190.48 R45.1@3411.43,4155.78
ATLK_NRST: R46.1 U6.28 | length 419.2
  Top Layer w6: U6.28@3415.69,4545.14 3415.69,4256.65 3485.43,4186.91 R46.1@3485.43,4154.78
ATLK_RX: CN2.10 CN7.10 R10.2 R48.2 | length 2463.7
  Top Layer w6: R48.2@3633.43,4092.78 3633.43,4033.98 3606.43,4006.98 v2(3606.43,3727.5) 3606.43,3662.02 3629.95,3638.5 3761.95,3638.5 3780.95,3657.5 3780.95,3727.5 3805.95,3752.5 4284.89,3752.5 CN2.10@4374.58,3842.18
  Bottom Layer w6: CN7.10@3288.43,3273.78 3338.95,3324.31 3338.95,3589.5 3382.95,3633.5 3544.95,3633.5 3606.43,3694.98 v2(3606.43,3727.5) ; CN2.10@4374.58,3842.18 4455.64,3842.18 4500.95,3887.5 R10.2@4793.95,3887.5
ATLK_SWCLK: R41.1 U6.25 | length 427
  Top Layer w6: R41.1@3263.43,4156.78 3263.43,4199.98 3356.64,4293.18 U6.25@3356.63,4545.14
ATLK_SWDIO: R44.1 U6.26 | length 404.5
  Top Layer w6: R44.1@3337.43,4156.78 3337.43,4245.78 3376.32,4284.67 U6.26@3376.32,4545.14
ATLK_SWO: R42.1 U6.13 | length 545.5
  Top Layer w6: R42.1@3263.95,4353.5 3263.95,4412.1 3223,4453.05 3223,4798 3245.73,4820.73 U6.13@3297.58,4820.73
ATLK_TX: CN2.8 CN7.8 R9.2 R47.2 | length 2396.3
  Top Layer w6: v2(3472.43,3577.5) 3472.43,3965.73 3559.43,4052.73 R47.2@3559.43,4092.78
  Bottom Layer w6: CN7.8@3388.43,3273.78 3437.95,3323.31 3437.95,3543.02 v2(3472.43,3577.5) ; v2@3472.43,3775.5 v2(3472.72,3775.78) 3500.43,3803.5 3718.49,3803.5 3738.95,3783.04 3791.95,3783.04 3828.95,3820.04 3828.95,3917.53 3846.03,3934.6 4115.19,3934.6 4119.61,3930.18 4187.89,3930.18 4224.58,3893.5 4325.89,3893.5 CN2.8@4374.58,3942.18 4516.14,3942.18 4537.45,3963.5 R9.2@4792.95,3963.5
AVDD18: C26.2 C27.2 C31.2 J10.4 J10.5 U8.6 | length 1197.3
  Top Layer w10: v5(7820,5158) 7795,5133 7795,4735.44 C27.2@7929,4601.44 7999.44,4601.44 C26.2@8004,4606 8057.68,4552.32 U8.6@8057.68,4503.89
  Bottom Layer w10: v5(7820,5158) 7820,5219 C31.2@7821,5220 7931.34,5220 J10.4@7988.04,5163.3 8038.04,5213.3 J10.5@8088.04,5213.3
AVREF+: J2.21 J3.8 L1.1 R17.1 | length 1870.4
  Top Layer w10: R17.1@6777.89,5258.16 6859.58,5258.16 ; v2(6833.95,5768.18) 6859.58,5742.56 6859.58,5258.16 ; L1.1@6859.12,5175.59 6859.58,5176.05 6859.58,5258.16
  Bottom Layer w10: J3.8@5953.28,5673.03 5953.28,5741.89 5979.58,5768.18 6561.58,5768.18 ; J2.21@6513.28,5973.03 6561.58,5924.74 6561.58,5768.18 ; v2(6833.95,5768.18) 6561.58,5768.18
BOOT0: CN2.4 CN7.4 J1.44 R18.1 R45.2 U3.94 | length 6612.4
  Top Layer w6: R45.2@3411.43,4094.78 v2(3411.43,3850.5) 3411.43,3579.11 3550.04,3440.5 3607.95,3440.5 3638.95,3409.5 3638.95,3324.31 CN7.4@3588.43,3273.78 ; v2(3790.95,3851.5) 3790.95,3817.53 3828.98,3779.5 4053.95,3779.5 4104.95,3830.5 4104.95,4036.5 4157.95,4089.5 4284.95,4089.5 4337.64,4142.18 CN2.4@4374.58,4142.18 ; v2(4176.58,4364.18) 4176.58,4418.12 4214.64,4456.18 R18.1@4311.58,4456.18 ; U3.94@6136.73,4428.38 6136.73,4232.73 6125.58,4221.58 6125.58,4199.06 6167.45,4157.18 6167.45,4035.31 6197.58,4005.18 6872.58,4005.18 6910.58,3967.18 6910.58,3705.3 6949.69,3666.18 7192.58,3666.18 7213.28,3645.48 J1.44@7213.28,3573.03
  Bottom Layer w6: v2(3411.43,3850.5) 3412.43,3851.5 v2(3790.95,3851.5) ; v2(4176.58,4364.18) 4176.58,4116.18 4201.58,4091.18 4286.58,4091.18 4337.58,4142.18 CN2.4@4374.58,4142.18 4426.58,4142.18 4466.58,4102.18 5707.82,4102.18 5731,4079 5773.64,4079 5781.64,4087 6006,4087 6018.82,4074.18 v2(6167.58,4074.18)
COL: R70.2 R85.2 U8.26 | length 380
  Top Layer w6: U8.26@8187.6,4354.29 8210.71,4354.29 8243,4322 8243,4268 v1(8313,4198) 8333,4198 8363,4168 R85.2@8363,4141.66
  Bottom Layer w6: R70.2@8252.66,4220 8291,4220 v1(8313,4198)
CRS: R84.2 U8.25 | length 258.6
  Top Layer w6: U8.25@8187.6,4334.6 8211.4,4334.6 8229,4317 8229,4245 8310,4164 R84.2@8310,4140.66
EGND: C5.1 J10.8 J10.13 J10.14 | length 1058
  Bottom Layer w10: C5.1@7824.56,5364 7987.34,5364 J10.8@7988.04,5363.3 8118.36,5493.62 J10.14@8218.04,5493.62 J10.13@8218.04,4883.38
